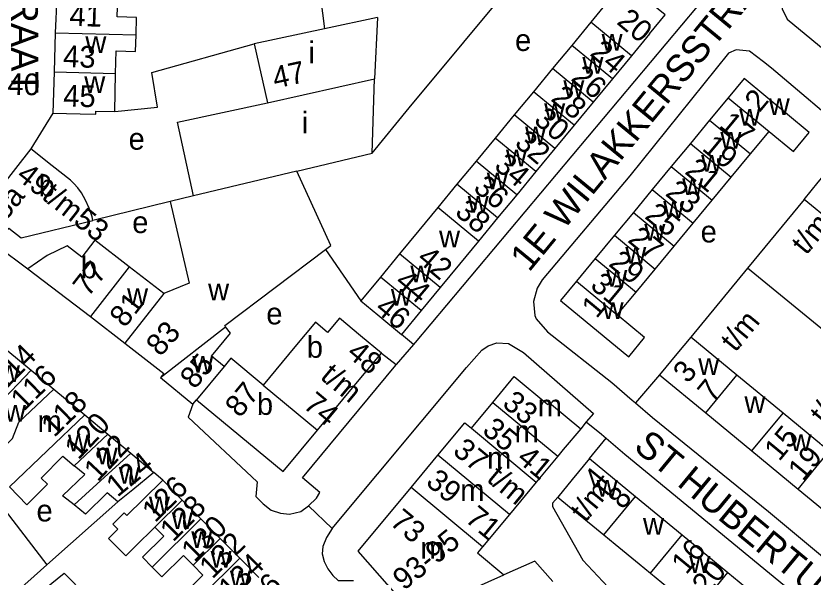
# Model space of a CAD drawing. Extents: x 161141 to 163125, y 381621 to 383200.
# Drawn here: x 162220.2 to 162366.8, y 382042.2 to 382145.5 of the extents above; entities that cross this region are included whole.
import ezdxf

# ---------------------------------------------------------------- set-up
doc = ezdxf.new("R2010")
doc.units = 0
for name, color, linetype in [('BLT_Basislijn', 7, 'Continuous'), ('BLT_Bebouwing', 7, 'Continuous'), ('BLT_Centroide', 7, 'Continuous'), ('BLT_Huisnummer', 7, 'Continuous'), ('BLT_Huisnummer_ tussenligend', 7, 'Continuous'), ('BLT_Huisnummer_reeks', 7, 'Continuous'), ('BLT_Onderverdeling_panden', 7, 'Continuous'), ('BLT_Straatnaam', 7, 'Continuous'), ('BLT_Vlakafsluiter', 7, 'Continuous')]:
    doc.layers.add(name, color=color, linetype=linetype)

msp = doc.modelspace()

# ---------------------------------------------------------------- linework, layer by layer
at = {"layer": 'BLT_Basislijn'}
for p, q in [((162275.74, 382152.2), (162276.96, 382143.08)), ((162227, 382127.59), (162222.95, 382120.98)), ((162248.54, 382111.3), (162234.37, 382107.85)), ((162365.16, 382111.71), (162354.76, 382099.08)), ((162216.47, 382103.34), (162222.37, 382098.93)), ((162277.12, 382102.49), (162283.62, 382093.05)), ((162354.76, 382099.08), (162344.32, 382086.38)), ((162422.74, 382043.07), (162354.76, 382099.08)), ((162293.32, 382085.04), (162291.1, 382086.88)), ((162293.32, 382085.04), (162290.16, 382081.34)), ((162287.43, 382083.43), (162290.16, 382081.34)), ((162338.59, 382079.44), (162334.15, 382074.25)), ((162325.1, 382070.76), (162324.07, 382069.52)), ((162325.68, 382064.03), (162328.75, 382067.8)), ((162247.2, 382060.05), (162245.56, 382061.46)), ((162216.09, 382057.23), (162225.91, 382044.48)), ((162238.96, 382056.05), (162225.91, 382044.48)), ((162225.91, 382044.48), (162215.44, 382035.2))]:
    msp.add_line(p, q, dxfattribs=at)
for points in [[(162401.95, 382191.98), (162398.46, 382194.68), (162395.63, 382191.81), (162370.34, 382161.04), (162363.85, 382153.43), (162361.77, 382150.62), (162361.1, 382149.22), (162361.1, 382146.74), (162362.02, 382144.86), (162380.2, 382129.91)], [(162285.74, 382120.21), (162292.54, 382128.55), (162323, 382165.23)], [(162345.49, 382147.22), (162293.63, 382085.4), (162293.32, 382085.04)], [(162238.36, 382127.85), (162246.24, 382128.7), (162245.22, 382135.06), (162264.04, 382140.31)], [(162357.7, 382137.01), (162355.11, 382138.99), (162352.68, 382139.21), (162351.25, 382138.58), (162333.1, 382116.06), (162316.98, 382096.91), (162316.07, 382095.4), (162315.4, 382092.92), (162315.64, 382090.35), (162315.9, 382089.71), (162317.94, 382087.32), (162329.79, 382078.01), (162333.54, 382074.78), (162334.15, 382074.25)], [(162374.49, 382122.89), (162373.95, 382123.33), (162359.15, 382135.85), (162357.7, 382137.01)], [(162278.37, 382051.18), (162303.05, 382080.81), (162305.91, 382083.94), (162307.03, 382084.79), (162308.63, 382085.34), (162310.8, 382085.18), (162313.57, 382083.52), (162326.41, 382072.32), (162325.1, 382070.76)], [(162272.88, 382060.51), (162290.07, 382081.24), (162290.16, 382081.34)], [(162252.73, 382074.01), (162251.85, 382071.63), (162264.57, 382059.74), (162264.32, 382057.06), (162265.66, 382055.72), (162267.17, 382054.55), (162268.84, 382053.96), (162270.51, 382053.8), (162272.61, 382054.3), (162274.03, 382055.3)], [(162334.15, 382074.25), (162337.26, 382071.57), (162358.62, 382054.3), (162378.15, 382037.96), (162379.85, 382036.77), (162386.45, 382031.28), (162396.07, 382023.68), (162401.71, 382018.71), (162402.15, 382018.36)], [(162325.1, 382070.76), (162327.9, 382068.54), (162328.75, 382067.8)], [(162328.75, 382067.8), (162332.19, 382064.86), (162396.8, 382011.68)], [(162274.03, 382055.3), (162275.45, 382056.73), (162276.12, 382057.81), (162272.88, 382060.51)], [(162319.84, 382056.94), (162318.88, 382055.83), (162318.88, 382055.19), (162324.45, 382045.34), (162354.82, 382012.97), (162359.86, 382007.3), (162359.47, 382005.81), (162356.92, 382002.62), (162357.4, 382001.66), (162376.24, 381985.85)], [(162278.37, 382051.18), (162277.29, 382049.53), (162276.62, 382047.85), (162276.54, 382046.51), (162276.87, 382045.09), (162277.54, 382043.75), (162278.46, 382042.49), (162279.47, 382041.57), (162282.31, 382041.57)]]:
    msp.add_lwpolyline(points, dxfattribs=at)
at = {"layer": 'BLT_Bebouwing'}
for p, q in [((162227.72, 382149.52), (162227.4, 382142.38)), ((162329.26, 382148.34), (162325.93, 382144.3)), ((162286.67, 382145.17), (162276.96, 382143.08)), ((162286.67, 382145.17), (162286.15, 382133.86)), ((162325.93, 382144.3), (162322.41, 382140.04)), ((162227.4, 382142.38), (162227.21, 382135.17)), ((162276.96, 382143.08), (162264.04, 382140.31)), ((162336.75, 382142.19), (162333.4, 382138.13)), ((162264.04, 382140.31), (162266.45, 382129.48)), ((162322.41, 382140.04), (162318.9, 382135.78)), ((162333.4, 382138.13), (162329.89, 382133.87)), ((162227.21, 382135.17), (162227, 382127.59)), ((162318.9, 382135.78), (162315.38, 382131.52)), ((162285.74, 382120.21), (162286.15, 382133.86)), ((162329.89, 382133.87), (162326.37, 382129.61)), ((162315.38, 382131.52), (162311.86, 382127.26)), ((162351.2, 382130.42), (162347.76, 382126.26)), ((162326.37, 382129.61), (162322.85, 382125.35)), ((162311.86, 382127.26), (162308.34, 382123)), ((162347.76, 382126.26), (162344.24, 382122.01)), ((162322.85, 382125.35), (162319.33, 382121.09)), ((162308.34, 382123), (162304.83, 382118.74)), ((162355.27, 382120.06), (162358.71, 382124.22)), ((162344.24, 382122.01), (162340.72, 382117.74)), ((162271.88, 382116.9), (162285.74, 382120.21)), ((162319.33, 382121.09), (162315.82, 382116.83)), ((162351.75, 382115.81), (162355.27, 382120.06)), ((162304.83, 382118.74), (162301.31, 382114.48)), ((162340.72, 382117.74), (162337.24, 382113.53)), ((162278.13, 382103.25), (162271.88, 382116.9)), ((162315.82, 382116.83), (162312.3, 382112.57)), ((162348.23, 382111.55), (162351.75, 382115.81)), ((162301.31, 382114.48), (162297.79, 382110.22)), ((162312.3, 382112.57), (162308.78, 382108.3)), ((162337.24, 382113.53), (162333.76, 382109.32)), ((162252.87, 382112.34), (162248.54, 382111.3)), ((162248.54, 382111.3), (162252.06, 382096.3)), ((162344.75, 382107.34), (162348.23, 382111.55)), ((162373.69, 382104.68), (162365.16, 382111.71)), ((162297.79, 382110.22), (162294.27, 382105.96)), ((162308.78, 382108.3), (162305.26, 382104.04)), ((162333.76, 382109.32), (162330.27, 382105.1)), ((162341.26, 382103.12), (162344.75, 382107.34)), ((162294.27, 382105.96), (162290.76, 382101.7)), ((162305.26, 382104.04), (162301.75, 382099.78)), ((162330.27, 382105.1), (162326.76, 382100.86)), ((162277.12, 382102.49), (162278.13, 382103.25)), ((162337.77, 382098.9), (162341.26, 382103.12)), ((162290.76, 382101.7), (162287.24, 382097.43)), ((162326.76, 382100.86), (162323.28, 382096.64)), ((162301.75, 382099.78), (162298.23, 382095.52)), ((162222.37, 382098.93), (162233.92, 382090.14)), ((162247.37, 382094.4), (162241.05, 382099.31)), ((162334.27, 382094.66), (162337.77, 382098.9)), ((162287.24, 382097.43), (162283.62, 382093.05)), ((162252.06, 382096.3), (162247.37, 382094.4)), ((162298.23, 382095.52), (162294.71, 382091.26)), ((162330.78, 382090.44), (162334.27, 382094.66)), ((162294.71, 382091.26), (162291.1, 382086.88)), ((162233.92, 382090.14), (162240.23, 382085.23)), ((162352.8, 382079.38), (162344.32, 382086.38)), ((162240.23, 382085.23), (162247.4, 382079.66)), ((162218.71, 382083.85), (162222.97, 382080.3)), ((162271.51, 382084.57), (162265.68, 382077.55)), ((162281.5, 382076.28), (162287.43, 382083.43)), ((162258.47, 382080.98), (162256.16, 382082.89)), ((162222.97, 382080.3), (162227.19, 382076.78)), ((162338.59, 382079.44), (162347.07, 382072.43)), ((162361.29, 382072.37), (162352.8, 382079.38)), ((162227.19, 382076.78), (162232.86, 382072.05)), ((162275.67, 382069.26), (162281.5, 382076.28)), ((162253.42, 382074.83), (162269.33, 382061.62)), ((162303.97, 382069.6), (162307.91, 382074.36)), ((162232.86, 382072.05), (162237.09, 382068.53)), ((162347.07, 382072.43), (162355.56, 382065.43)), ((162369.78, 382065.36), (162361.29, 382072.37)), ((162269.33, 382061.62), (162275.67, 382069.26)), ((162237.09, 382068.53), (162241.31, 382065)), ((162241.31, 382065), (162245.56, 382061.46)), ((162292.86, 382058.68), (162297.81, 382064.64)), ((162319.86, 382064.45), (162315.91, 382059.69)), ((162355.56, 382065.43), (162364.05, 382058.42)), ((162325.68, 382064.03), (162334.16, 382057.05)), ((162250.8, 382056.4), (162247.2, 382060.05)), ((162315.91, 382059.69), (162310.97, 382053.73)), ((162364.05, 382058.42), (162372.54, 382051.41)), ((162334.16, 382057.05), (162342.72, 382050)), ((162254.23, 382052.92), (162250.8, 382056.4)), ((162257.79, 382049.32), (162254.23, 382052.92)), ((162310.97, 382053.73), (162306.02, 382047.77)), ((162342.72, 382050), (162351.16, 382043.05)), ((162261.38, 382045.68), (162257.79, 382049.32)), ((162306.02, 382047.77), (162305.1, 382046.66)), ((162305.1, 382046.66), (162309.95, 382042.63)), ((162264.9, 382042.12), (162261.38, 382045.68)), ((162351.16, 382043.05), (162359.53, 382036.17))]:
    msp.add_line(p, q, dxfattribs=at)
for points in [[(162336.75, 382142.19), (162339.63, 382145.68), (162335.77, 382148.86), (162327.66, 382155.56), (162324.77, 382152.05), (162329.26, 382148.34)], [(162242.29, 382142), (162242.37, 382145.18), (162238.82, 382145.27), (162238.91, 382148.87), (162240.24, 382148.83), (162240.26, 382149.11)], [(162238.54, 382134.85), (162238.65, 382139.03), (162242.21, 382138.94), (162242.29, 382142)], [(162238.36, 382127.85), (162238.54, 382134.85)], [(162358.71, 382124.22), (162363.21, 382120.5), (162366.12, 382124.01), (162354.11, 382133.94), (162351.2, 382130.42)], [(162252.87, 382112.34), (162249.9, 382125.93), (162266.45, 382129.48)], [(162227, 382127.59), (162231.99, 382127.46), (162234.89, 382127.38), (162234.91, 382127.94), (162238.36, 382127.85)], [(162222.95, 382120.98), (162212.03, 382107.11)], [(162230.26, 382115.23), (162226.88, 382117.89), (162222.95, 382120.98)], [(162365.16, 382111.71), (162367.75, 382114.86), (162370.93, 382118.71)], [(162234.37, 382107.85), (162234.23, 382108.51), (162233.65, 382110.11), (162233, 382111.54), (162232.24, 382112.91), (162231.57, 382113.81), (162230.82, 382114.66), (162230.26, 382115.23)], [(162216.47, 382103.34), (162218.87, 382106.41), (162221.16, 382104.61), (162234.37, 382107.85)], [(162241.05, 382099.31), (162234.74, 382104.23), (162232.3, 382101.09), (162229.64, 382103.16), (162225.94, 382101.36), (162222.37, 382098.93)], [(162258.76, 382088.26), (162258.59, 382088.49), (162277.12, 382102.49)], [(162323.28, 382096.64), (162320.37, 382093.12), (162332.9, 382082.76), (162335.81, 382086.28), (162330.78, 382090.44)], [(162283.62, 382093.05), (162286.74, 382090.48), (162291.1, 382086.88)], [(162287.43, 382083.43), (162283.58, 382086.62), (162279.69, 382089.85), (162277.52, 382087.24), (162275.27, 382089.1), (162271.51, 382084.57)], [(162256.16, 382082.89), (162259.65, 382087.09), (162258.76, 382088.26)], [(162344.32, 382086.38), (162341.77, 382083.3), (162338.59, 382079.44)], [(162265.68, 382077.55), (162259.73, 382082.5), (162258.47, 382080.98)], [(162247.4, 382079.66), (162246.8, 382078.93)], [(162246.8, 382078.93), (162252.73, 382074.01)], [(162307.91, 382074.36), (162311.86, 382079.11), (162318.05, 382073.97), (162318.31, 382074.29), (162324.07, 382069.52)], [(162252.73, 382074.01), (162253.42, 382074.83)], [(162297.81, 382064.64), (162302.75, 382070.61), (162303.97, 382069.6)], [(162324.07, 382069.52), (162320.87, 382065.67), (162319.86, 382064.45)], [(162218.99, 382058.85), (162222.21, 382055.52), (162225.98, 382059.32), (162224.82, 382060.42), (162228.82, 382064.44), (162230.91, 382062.69)], [(162325.68, 382064.03), (162322.5, 382060.17), (162319.84, 382056.94)], [(162230.88, 382055.5), (162228.78, 382057.19), (162232.85, 382061.08), (162230.91, 382062.69)], [(162245.56, 382061.46), (162241.7, 382058.29), (162238.96, 382056.05)], [(162247.2, 382060.05), (162243.64, 382056.54), (162240.61, 382053.54), (162240.13, 382054.03), (162238.05, 382051.98), (162238.97, 382051.04), (162237.24, 382049.33), (162240.4, 382046.13), (162242.13, 382047.84), (162245.76, 382051.42)], [(162294.65, 382033.84), (162283.16, 382046.98), (162292.86, 382058.68)], [(162238.96, 382056.05), (162236.97, 382057.7), (162232.97, 382053.81), (162230.88, 382055.5)], [(162319.84, 382056.94), (162321.99, 382055.17), (162326.28, 382051.66), (162328.33, 382049.97)], [(162245.76, 382051.42), (162247.41, 382049.75), (162243.48, 382045.87), (162245.27, 382044.07)], [(162328.33, 382049.97), (162330.39, 382048.27), (162334.82, 382044.65), (162336.9, 382042.93)], [(162245.27, 382044.07), (162247.05, 382042.26), (162251.03, 382046.2), (162252.81, 382044.4)], [(162318.92, 382041.38), (162315.62, 382045.14), (162309.95, 382042.63)], [(162252.81, 382044.4), (162254.59, 382042.6), (162250.63, 382038.69), (162252.44, 382036.86)], [(162210.2, 382027.75), (162214.09, 382030.89), (162229.04, 382042.96), (162233.09, 382038.84), (162224.67, 382032.05)], [(162336.9, 382042.93), (162338.98, 382041.22), (162343.24, 382037.73), (162345.35, 382035.99)]]:
    msp.add_lwpolyline(points, dxfattribs=at)
at = {"layer": 'BLT_Onderverdeling_panden'}
for p, q in [((162333.4, 382138.13), (162325.93, 382144.3)), ((162227.4, 382142.38), (162242.29, 382142)), ((162329.89, 382133.87), (162322.41, 382140.04)), ((162227.21, 382135.17), (162238.54, 382134.85)), ((162326.37, 382129.61), (162318.9, 382135.78)), ((162266.45, 382129.48), (162286.15, 382133.86)), ((162322.85, 382125.35), (162315.38, 382131.52)), ((162351.2, 382130.42), (162358.71, 382124.22)), ((162319.33, 382121.09), (162311.86, 382127.26)), ((162347.76, 382126.26), (162355.27, 382120.06)), ((162315.82, 382116.83), (162308.34, 382123)), ((162344.24, 382122.01), (162351.75, 382115.81)), ((162312.3, 382112.57), (162304.83, 382118.74)), ((162340.72, 382117.74), (162348.23, 382111.55)), ((162271.88, 382116.9), (162252.87, 382112.34)), ((162308.78, 382108.3), (162301.31, 382114.48)), ((162337.24, 382113.53), (162344.75, 382107.34)), ((162305.26, 382104.04), (162297.79, 382110.22)), ((162333.76, 382109.32), (162341.26, 382103.12)), ((162330.27, 382105.1), (162337.77, 382098.9)), ((162298.23, 382095.52), (162290.76, 382101.7)), ((162326.76, 382100.86), (162334.27, 382094.66)), ((162241.05, 382099.31), (162233.92, 382090.14)), ((162294.71, 382091.26), (162287.24, 382097.43)), ((162323.28, 382096.64), (162330.78, 382090.44)), ((162247.37, 382094.4), (162240.23, 382085.23)), ((162246.8, 382078.93), (162258.76, 382088.26)), ((162258.47, 382080.98), (162253.42, 382074.83)), ((162212.57, 382069.33), (162222.97, 382080.3)), ((162347.07, 382072.43), (162352.8, 382079.38)), ((162265.68, 382077.55), (162275.67, 382069.26)), ((162307.91, 382074.36), (162319.86, 382064.45)), ((162218.99, 382058.85), (162232.86, 382072.05)), ((162355.56, 382065.43), (162361.29, 382072.37)), ((162303.97, 382069.6), (162315.91, 382059.69)), ((162230.91, 382062.69), (162237.09, 382068.53)), ((162230.88, 382055.5), (162241.31, 382065)), ((162310.97, 382053.73), (162297.81, 382064.64)), ((162364.05, 382058.42), (162369.78, 382065.36)), ((162306.02, 382047.77), (162292.86, 382058.68)), ((162328.33, 382049.97), (162334.16, 382057.05)), ((162245.76, 382051.42), (162250.8, 382056.4)), ((162245.27, 382044.07), (162254.23, 382052.92)), ((162336.9, 382042.93), (162342.72, 382050)), ((162252.81, 382044.4), (162257.79, 382049.32)), ((162252.44, 382036.86), (162261.38, 382045.68)), ((162300.6, 382038.49), (162309.95, 382042.63)), ((162345.35, 382035.99), (162351.16, 382043.05))]:
    msp.add_line(p, q, dxfattribs=at)
msp.add_lwpolyline([(162212.93, 382061.05), (162219.55, 382067.72), (162220.75, 382070.7), (162227.19, 382076.78)], dxfattribs=at)
at = {"layer": 'BLT_Vlakafsluiter'}
msp.add_line((162278.37, 382051.18), (162274.03, 382055.3), dxfattribs=at)

# ---------------------------------------------------------------- texts
at = {"layer": 'BLT_Centroide'}
for s, p in [('e', (162311.99, 382139.01)), ('w', (162327.91, 382139.09)), ('w', (162232.97, 382138.62)), ('i', (162274.01, 382136.75)), ('w', (162324.38, 382134.81)), ('w', (162232.77, 382131.28)), ('w', (162320.88, 382130.56)), ('w', (162358.66, 382127.22)), ('w', (162317.35, 382126.31)), ('i', (162272.77, 382123.84)), ('w', (162353.23, 382125.25)), ('w', (162313.84, 382122.03)), ('e', (162240.92, 382120.85)), ('w', (162349.76, 382121.03)), ('w', (162310.32, 382117.78)), ('w', (162346.23, 382116.78)), ('b', (162224.38, 382112.25)), ('w', (162306.8, 382113.53)), ('w', (162342.73, 382112.53)), ('w', (162303.29, 382109.25)), ('w', (162339.25, 382108.31)), ('e', (162241.59, 382105.51)), ('w', (162335.77, 382104.09)), ('e', (162346.13, 382103.79)), ('w', (162298.02, 382102.88)), ('w', (162332.27, 382099.88)), ('b', (162232.13, 382097.19)), ('w', (162292.73, 382096.47)), ('w', (162328.77, 382095.66)), ('w', (162240.64, 382092.27)), ('w', (162255.54, 382093.12)), ('w', (162289.16, 382092.16)), ('w', (162328.09, 382089.69)), ('e', (162266.25, 382088.71)), ('b', (162273.7, 382082.57)), ('w', (162252.64, 382079.83)), ('w', (162345.7, 382079.41)), ('w', (162217.08, 382078.11)), ('b', (162264.52, 382072.06)), ('m', (162316.18, 382071.78)), ('w', (162354.18, 382072.41)), ('w', (162218.17, 382070.8)), ('m', (162224.17, 382068.89)), ('m', (162311.91, 382067.03)), ('w', (162229.76, 382065.34)), ('w', (162362.66, 382065.41)), ('w', (162235.05, 382062.94)), ('m', (162306.86, 382062.16)), ('w', (162239.12, 382059.41)), ('w', (162327.01, 382057)), ('m', (162301.91, 382056.22)), ('w', (162244.66, 382053.94)), ('e', (162223.98, 382052.46)), ('w', (162248.86, 382051.05)), ('w', (162335.53, 382050)), ('w', (162252.44, 382047.59)), ('m', (162294.59, 382045.58)), ('w', (162256, 382043.97)), ('w', (162344.04, 382043)), ('w', (162259.55, 382040.34))]:
    msp.add_text(s, height=4, dxfattribs=at).set_placement(p)
at = {"layer": 'BLT_Huisnummer'}
for s, rotation, p in [('20', 319.9717, (162330.52, 382144.13)), ('24', 319.9712, (162325.59, 382138.35)), ('47', 12.4014, (162267.87, 382132.07)), ('45', 358.4989, (162228.86, 382128.81)), ('28', 319.9719, (162318.41, 382130)), ('2', 50.426, (162356.97, 382127.58)), ('17', 320.4273, (162349.33, 382125.13)), ('32', 319.9719, (162311.72, 382121.74)), ('21', 320.4318, (162343.04, 382116.59)), ('36', 319.9719, (162304.12, 382113.48)), ('25', 320.4281, (162335.66, 382108.38)), ('42', 319.9719, (162293.74, 382100.47)), ('77', 52.1159, (162233.5, 382093.6)), ('31', 320.4289, (162325.62, 382095.55)), ('1', 50.416, (162326.99, 382089.65)), ('46', 320.4672, (162286.02, 382091.28)), ('83', 48.4599, (162246.76, 382082.63)), ('116', 44.4074, (162221.62, 382072.6)), ('87', 50.3008, (162261.39, 382071.36)), ('33', 320.3254, (162309.45, 382073.8)), ('120', 46.7689, (162231.68, 382063.64)), ('35', 320.3257, (162305.76, 382068.86)), ('124', 39.359, (162238.87, 382056.81)), ('126', 44.6434, (162245.79, 382052.1)), ('132', 44.637, (162256.31, 382041.74)), ('136', 44.6434, (162263.09, 382034.24))]:
    msp.add_text(s, height=4, rotation=rotation, dxfattribs=at).set_placement(p)
at = {"layer": 'BLT_Huisnummer_ tussenligend'}
for s, rotation, p in [('41', 358.1179, (162230, 382143.65)), ('43', 358.1179, (162228.84, 382136.09)), ('26', 319.9712, (162322.1, 382133.76)), ('30', 319.9719, (162315.25, 382125.96)), ('19', 320.4273, (162346.21, 382120.87)), ('34', 319.9719, (162307.94, 382117.53)), ('23', 320.4318, (162339.45, 382112.57)), ('38', 319.9719, (162300.74, 382109.04)), ('27', 320.4281, (162332.53, 382104.01)), ('29', 320.4281, (162329.02, 382099.62)), ('44', 319.9681, (162289.7, 382096.14)), ('81', 52.112, (162240.24, 382087.94)), ('114', 45.4667, (162218, 382076.31)), ('85', 50.5622, (162253.1, 382076.62)), ('118', 44.4074, (162227.23, 382067.79)), ('122', 46.7689, (162235.24, 382059.62)), ('128', 44.6357, (162249.1, 382048.57)), ('130', 44.6357, (162253.02, 382044.81)), ('134', 44.637, (162259.81, 382037.89))]:
    msp.add_text(s, height=4, rotation=rotation, dxfattribs=at).set_placement(p)
at = {"layer": 'BLT_Huisnummer_reeks'}
for s, rotation, p in [('36-38-40', 358.8071, (162203.16, 382131.29)), ('49t/m53', 321.7781, (162220.05, 382115.64)), ('75a', 51.7781, (162216.51, 382105.3)), ('t/m', 50.4667, (162365.54, 382101.32)), ('t/m', 50.4667, (162352.51, 382083.45)), ('48', 320.299, (162280.83, 382083.04)), ('3', 50.4688, (162343.79, 382077.68)), ('t/m', 320.2984, (162275.98, 382078.81)), ('7', 50.4593, (162348.3, 382074.15)), ('74', 320.2911, (162272.82, 382073.54)), ('t/m', 50.4667, (162368.94, 382070.05)), ('15', 50.4642, (162360.58, 382063.36)), ('37', 320.3254, (162300.34, 382065.07)), ('19', 50.4602, (162364.94, 382059.69)), ('41', 320.3254, (162312.11, 382063.67)), ('39', 320.3257, (162295.39, 382059.37)), ('t/m', 320.3257, (162306.58, 382060)), ('4', 50.5437, (162327.37, 382057.97)), ('t/m', 50.5528, (162324.91, 382052.13)), ('8', 50.5528, (162331.79, 382054.49)), ('71', 320.3279, (162302.62, 382052.61)), ('73', 320.3279, (162288.78, 382052.02)), ('93-95', 39.0278, (162291.56, 382039.63)), ('16', 50.5332, (162343.49, 382042.53)), ('20', 50.5418, (162347.27, 382038.68))]:
    msp.add_text(s, height=4, rotation=rotation, dxfattribs=at).set_placement(p)
at = {"layer": 'BLT_Straatnaam'}
for s, rotation, p in [('SCHALMSTRAAT', 270.2169, (162219.14, 382185.41)), ('1E WILAKKERSSTRAAT', 50.5791, (162314.57, 382098.18)), ('ST HUBERTUSSTRAAT', 320.4305, (162333.59, 382065.82))]:
    msp.add_text(s, height=5, rotation=rotation, dxfattribs=at).set_placement(p)

doc.saveas('drawing.dxf')
